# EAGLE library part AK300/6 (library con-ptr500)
CONNECTOR
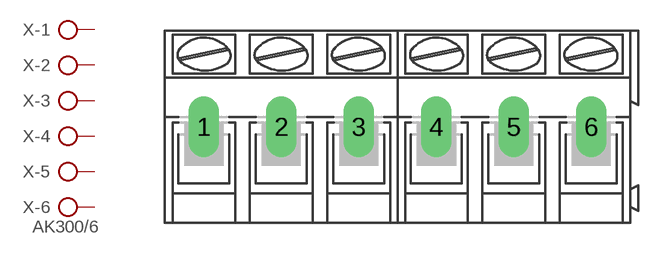
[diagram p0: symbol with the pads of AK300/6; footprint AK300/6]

Designator prefix X; gates -1=KL -2=KL -3=KL -4=KL -5=KL -6=KLV

## AK300/6 (OC_FARNELL: unknown; OC_NEWARK: unknown)  [AK300/6]
1  -1:KL  pas
2  -2:KL  pas
3  -3:KL  pas
4  -4:KL  pas
5  -5:KL  pas
6  -6:KL  pas

## Footprint AK300/6 (pad centres in mm)
CONNECTOR
drill 1.321 long: 1 -12.522,0; 2 -7.518,0; 3 -2.515,0; 4 2.515,0; 5 7.518,0; 6 12.522,0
